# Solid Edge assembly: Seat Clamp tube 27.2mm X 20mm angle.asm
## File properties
Author: morva
Template: iso metric assembly.asm
Last saved by: morva
Revision: 2
Application: Solid Edge
Username: morva
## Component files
Seat Clamp tube 27.2mm X 20mm angle.par
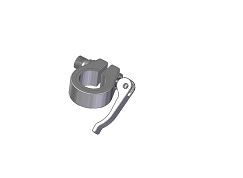
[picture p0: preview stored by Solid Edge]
